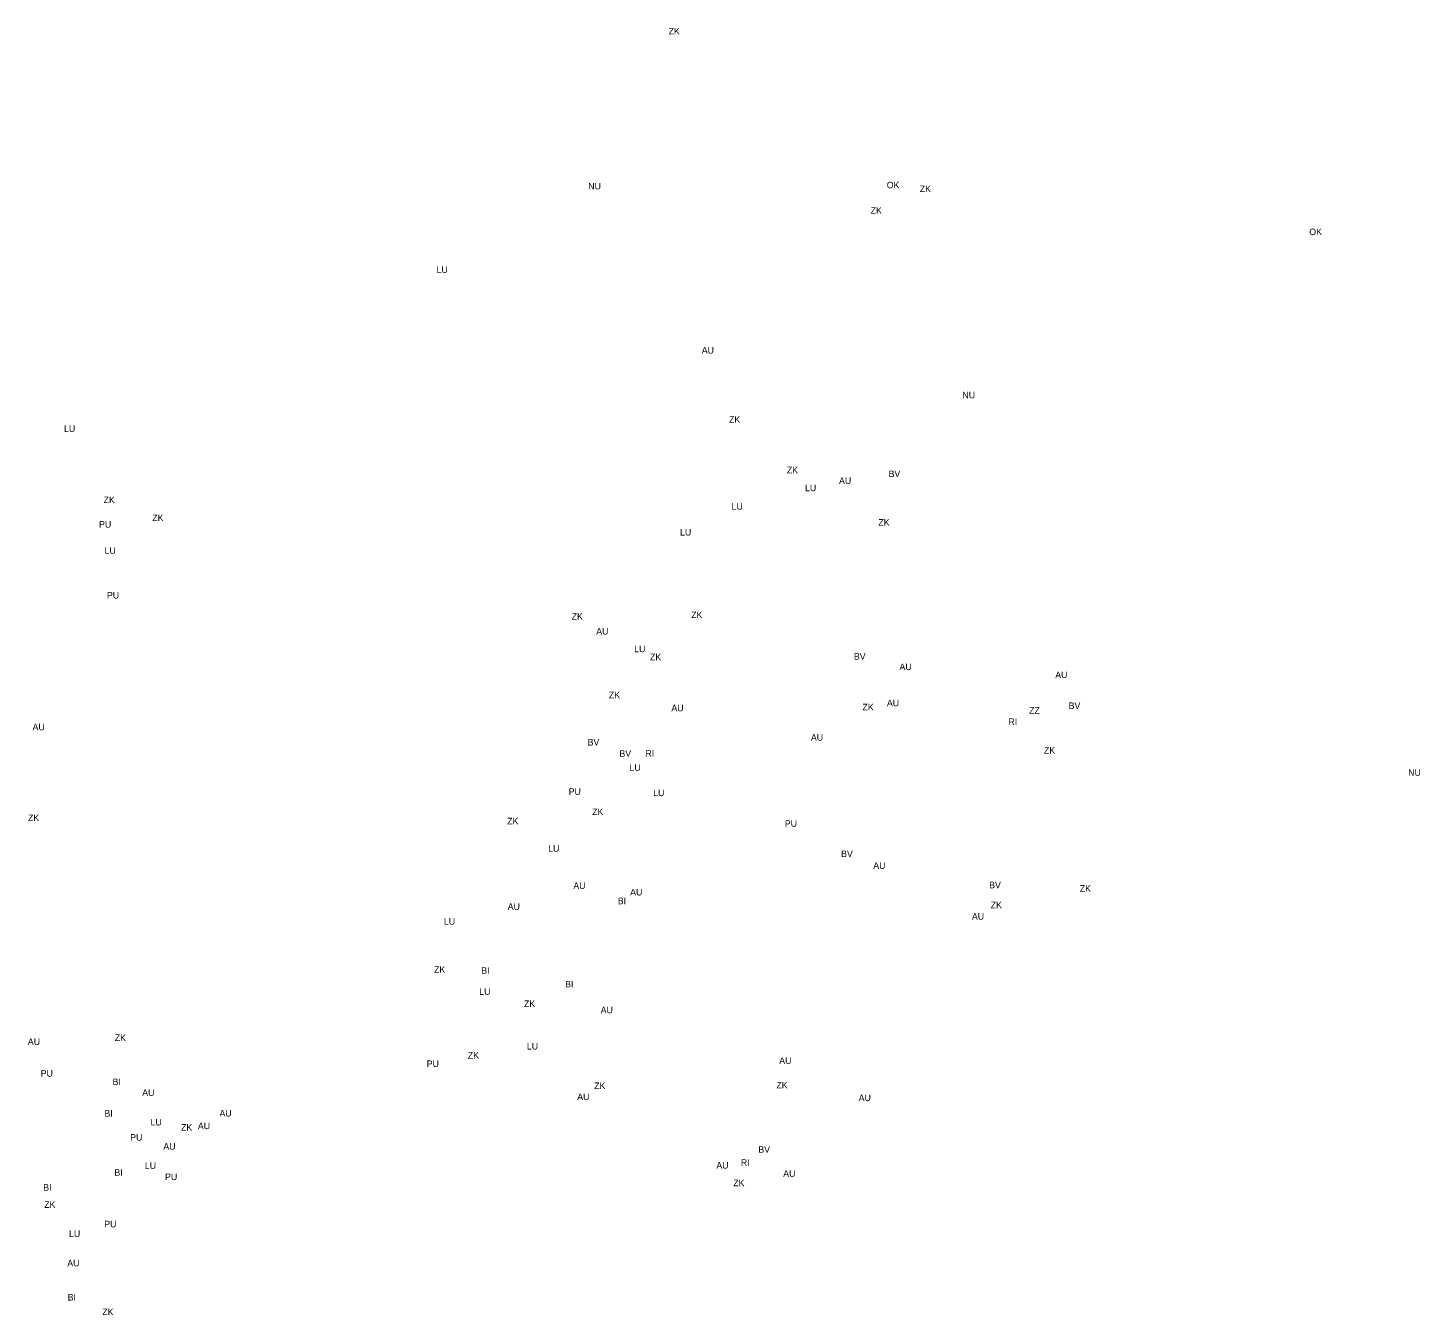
# Model space of a CAD drawing. Extents: x -439151 to -433911, y -1129946 to -1121460.
# Drawn here: x -436517 to -434394, y -1123689 to -1121726 of the extents above; entities that cross this region are included whole.
import ezdxf

# ---------------------------------------------------------------- set-up
doc = ezdxf.new("R2010")
doc.units = 0
doc.layers.add('POPIS PRESTAVBA', color=7, linetype='Continuous')

msp = doc.modelspace()

# ---------------------------------------------------------------- texts
at = {"layer": 'POPIS PRESTAVBA'}
for s, p in [('ZK', (-435540, -1121736)), ('NU', (-435662.4, -1121972.3)), ('OK', (-435207.4, -1121970.7)), ('ZK', (-435157, -1121976.4)), ('ZK', (-435231.9, -1122009.4)), ('OK', (-434563.3, -1122042)), ('LU', (-435893.6, -1122099.7)), ('AU', (-435489.4, -1122222.6)), ('NU', (-435092, -1122290.9)), ('LU', (-436461.5, -1122342.1)), ('ZK', (-435447.9, -1122328.2)), ('ZK', (-435359.7, -1122405.2)), ('AU', (-435280.2, -1122421.5)), ('BV', (-435204.6, -1122411)), ('LU', (-435332, -1122432.4)), ('ZK', (-436401.2, -1122450.6)), ('LU', (-435443.9, -1122460.5)), ('PU', (-436408.1, -1122488)), ('ZK', (-436327, -1122478)), ('ZK', (-435220.2, -1122485)), ('LU', (-435522.6, -1122500)), ('LU', (-436399.7, -1122527.8)), ('PU', (-436396.1, -1122596.1)), ('ZK', (-435687.7, -1122628.3)), ('ZK', (-435505.5, -1122626)), ('AU', (-435650.2, -1122651)), ('LU', (-435592.4, -1122677.9)), ('ZK', (-435568.3, -1122690.3)), ('BV', (-435257.5, -1122689.3)), ('AU', (-435188, -1122705.2)), ('AU', (-434950.5, -1122717.4)), ('ZK', (-435631, -1122748.2)), ('AU', (-435535.7, -1122768)), ('ZK', (-435244.5, -1122766.6)), ('AU', (-435207.2, -1122760.3)), ('BV', (-434930.2, -1122764.6)), ('RI', (-435021.9, -1122788.9)), ('ZZ', (-434990.3, -1122771.6)), ('AU', (-436509.5, -1122797)), ('BV', (-435663.4, -1122820.2)), ('AU', (-435323, -1122812.8)), ('BV', (-435614.9, -1122837.4)), ('RI', (-435575.2, -1122837.1)), ('ZK', (-434967.8, -1122832.6)), ('LU', (-435599.5, -1122858.9)), ('NU', (-434412.6, -1122866.3)), ('PU', (-435692.3, -1122895.5)), ('LU', (-435563.4, -1122897.4)), ('ZK', (-436516.4, -1122935.4)), ('ZK', (-435656.5, -1122926.3)), ('ZK', (-435786, -1122940.4)), ('PU', (-435362.8, -1122944.2)), ('LU', (-435723.6, -1122982.1)), ('BV', (-435277, -1122990.3)), ('AU', (-435227.9, -1123008.3)), ('AU', (-435685.2, -1123038.9)), ('BV', (-435051.3, -1123037.9)), ('ZK', (-434913.2, -1123043.1)), ('BI', (-435617.4, -1123062.2)), ('AU', (-435598.5, -1123048.8)), ('AU', (-435785.2, -1123070.9)), ('AU', (-435077.6, -1123085.8)), ('ZK', (-435048.9, -1123068.3)), ('LU', (-435882.5, -1123093.3)), ('ZK', (-435897.5, -1123166.7)), ('BI', (-435825.6, -1123168.2)), ('BI', (-435697.7, -1123189.1)), ('LU', (-435828.6, -1123200.4)), ('ZK', (-435760.4, -1123218.9)), ('AU', (-435643.5, -1123228.4)), ('AU', (-436516.7, -1123276.8)), ('ZK', (-436384.2, -1123270.7)), ('ZK', (-435846, -1123297.5)), ('LU', (-435756.1, -1123283.7)), ('PU', (-435908.6, -1123310.4)), ('AU', (-435371.3, -1123305.8)), ('PU', (-436497.1, -1123325.1)), ('BI', (-436387.6, -1123337.9)), ('AU', (-436342.3, -1123354.4)), ('AU', (-435679.2, -1123360.8)), ('ZK', (-435653.4, -1123343.9)), ('ZK', (-435375.6, -1123343)), ('AU', (-435250.2, -1123362.4)), ('BI', (-436399.9, -1123386)), ('LU', (-436329.6, -1123399.5)), ('AU', (-436224.6, -1123385.8)), ('PU', (-436360.7, -1123422.7)), ('ZK', (-436283.2, -1123407.5)), ('AU', (-436257.5, -1123405.1)), ('AU', (-436310.1, -1123436.3)), ('BV', (-435403.2, -1123441.2)), ('LU', (-436338.4, -1123465.8)), ('AU', (-435467.1, -1123465.2)), ('RI', (-435429.8, -1123461.1)), ('BI', (-436384.7, -1123476.2)), ('PU', (-436307.5, -1123482.8)), ('AU', (-435365.2, -1123477.9)), ('BI', (-436493.3, -1123498.9)), ('ZK', (-435441.4, -1123492.1)), ('ZK', (-436491.7, -1123525.1)), ('LU', (-436453.9, -1123569.6)), ('PU', (-436400.3, -1123554.8)), ('AU', (-436456.6, -1123614.3)), ('BI', (-436456, -1123666.4)), ('ZK', (-436403.2, -1123688.7))]:
    msp.add_text(s, height=10, dxfattribs=at).set_placement(p)

doc.saveas('drawing.dxf')
